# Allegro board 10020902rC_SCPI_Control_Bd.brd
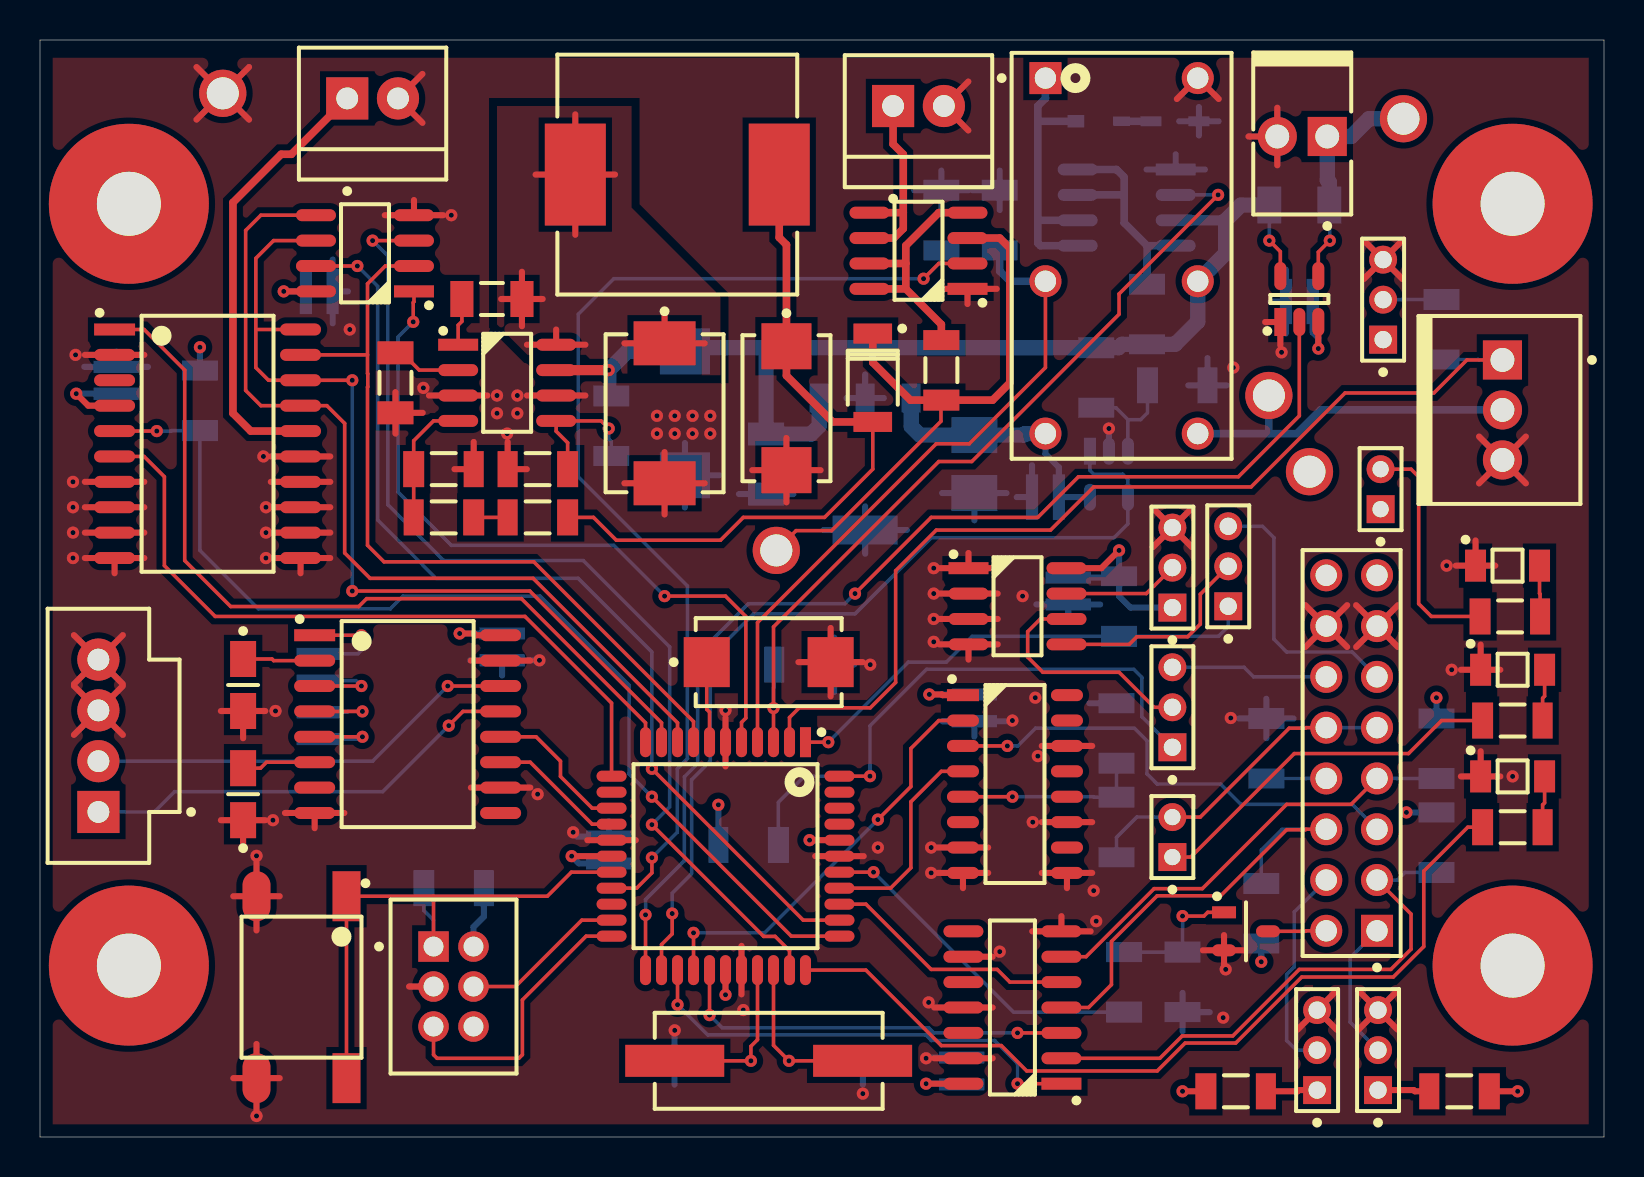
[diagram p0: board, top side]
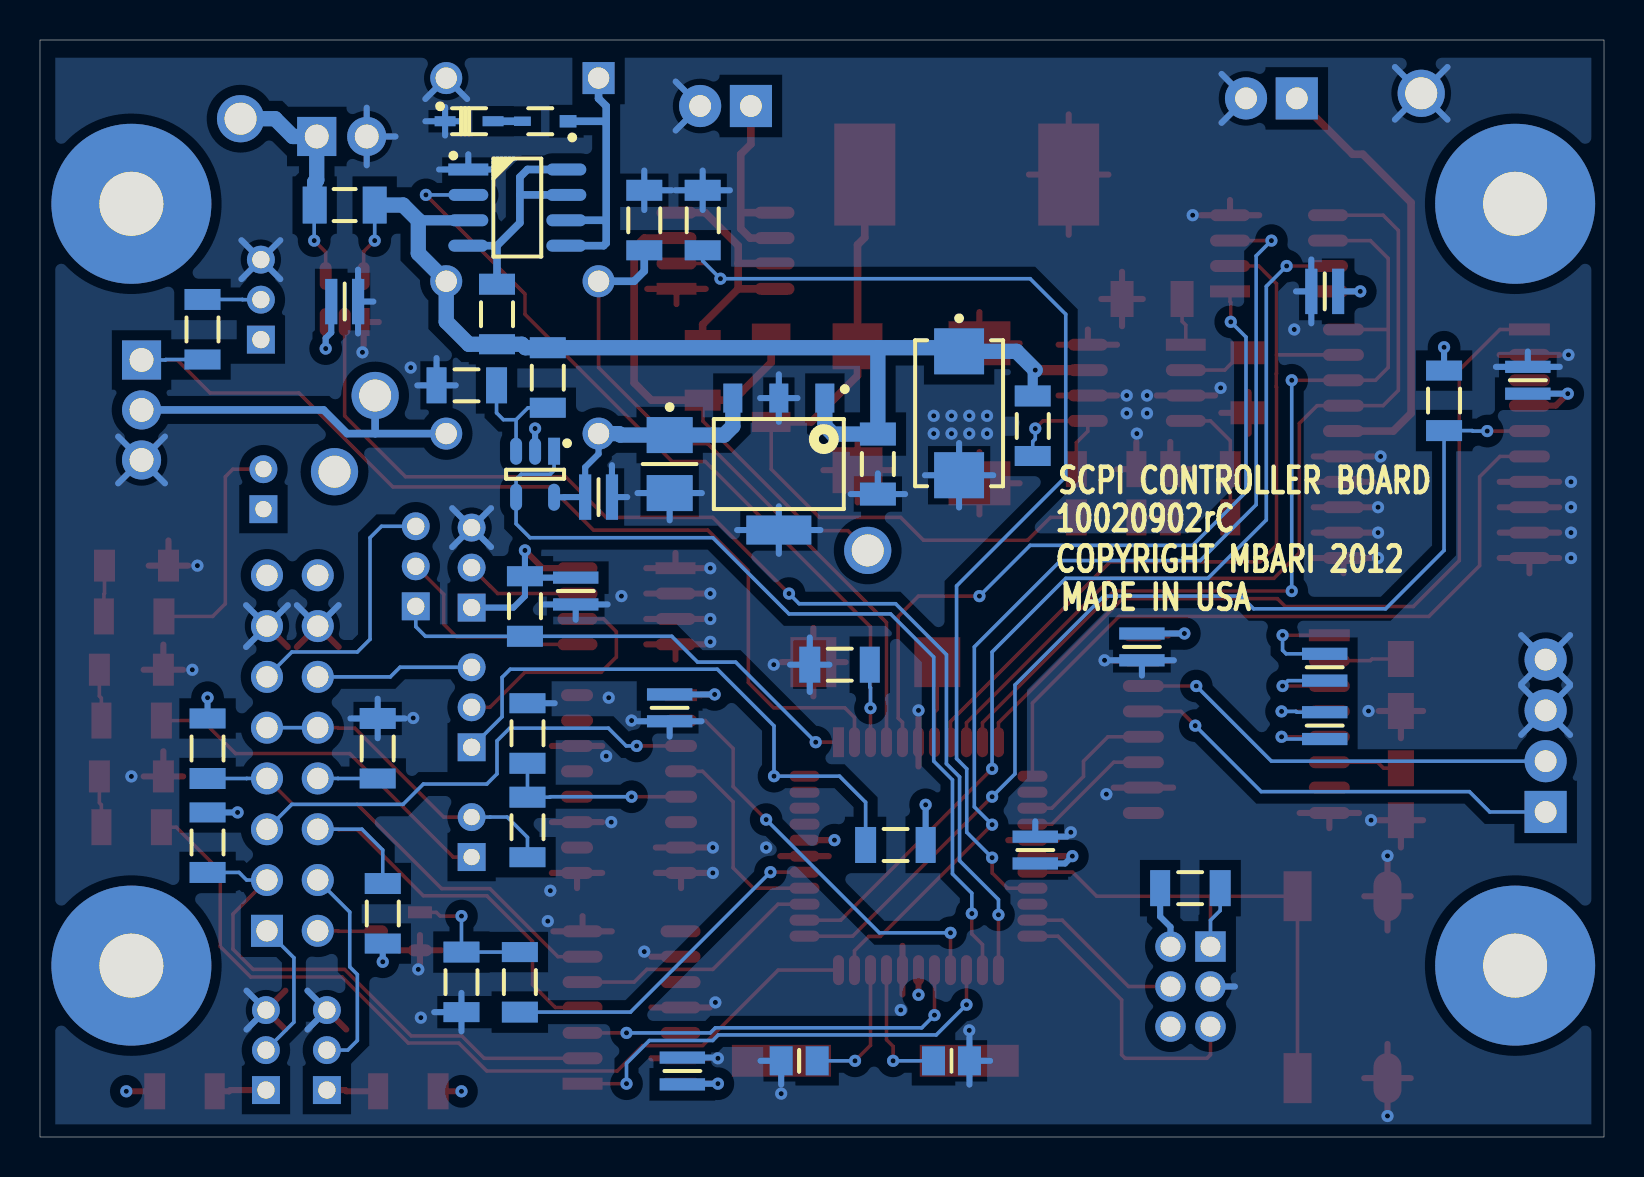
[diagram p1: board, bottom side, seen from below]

Outline 78.23 x 54.86 mm; copper layers: TOP, GND1, GND2, BOTTOM. Coordinates in mm from the lower left corner of the outline.
Outline path: 0,54.86 0,0 78.23,0 78.23,54.86 0,54.86

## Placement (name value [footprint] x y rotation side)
C1  0.1uF  [CAPC1320X76N]  28.45 14.35 90 bottom
C2  15pF  [CAPC2012X88N]  32.64 3.81 180 bottom
C3  15pF  [CAPC2012X88N]  40.26 3.81 0 bottom
C4  0.1uF  [CAPC1320X76N]  13.97 23.5 270 bottom
C5  0.1uF  [CAPC1320X76N]  13.97 20.57 270 bottom
C6  0.1uF  [CAPC1320X76N]  23.11 24.51 270 bottom
C7  0.1uF  [CAPMP3216X180N]  10.16 17.14 90 top
C8  0.1uF  [CAPMP3216X180N]  10.16 22.61 270 top
C9  10uF  [CAPMP7343X310N]  36.45 23.75 0 top
C10  0.1uF  [CAPC1320X76N]  13.97 42.29 180 bottom
C11  0.1uF  [CAPC1320X76N]  51.44 27.3 270 bottom
C12  0.1uF  [CAPC1320X76N]  46.1 3.3 90 bottom
C13  0.1uF  [CAPC1320X76N]  46.74 21.46 270 bottom
C14  0.1uF  [CAPC1320X76N]  3.81 37.85 90 bottom
C15  1.0uF  [CAPC3216X110N]  36.32 33.66 270 bottom
C16  10uF  [CAPMP3528X120N]  46.74 33.66 270 bottom
C17  0.1uF  [CAPC1320X76N]  62.99 41.78 180 bottom
C18  0.10uF  [CAPC3216X180N]  22.61 41.91 0 top
C19  100uF  [CAPMP7343X430N]  32.26 36.2 270 bottom
C20  68uF  [CAPMP7343X310N]  37.34 36.45 270 top
C21  0.10uF  [CAPC3216X180N]  17.78 37.72 270 top
C22  0.1uF  [CAPC1320X76N]  50.29 32 180 bottom
D1  LTST-C150KGKT  [LED_LTST-C150XXX]  73.66 23.37 0 top
D2  LTST-C150KGKT  [LED_LTST-C150XXX]  73.66 18.03 0 top
D3  LTST-C150KGKT  [LED_LTST-C150XXX]  73.41 28.57 0 top
D4  PMEG3050EP,115  [SODFL4725X110N]  41.66 37.97 270 top
D5  B550C-13-F  [DIOM7959X250N]  31.24 36.2 270 top
D6  BZX384-C3V3,115  [SOD2513X110N]  56.77 50.8 180 bottom
D7  DB2J31700L  [SODFL2513X80N]  52.96 50.8 0 bottom
J1  68602-116HLF  [HDRV16W64P254_2X8_858H]  66.88 10.31 90 top
J2  87831-0620  [MOLEX_87831-0620]  19.68 9.53 270 top
J3  70543-0003  [MOLEX_70543-4PIN]  2.92 20.07 270 top
J4  70543-0001  [MOLEX_70543-2PIN]  15.37 51.94 180 top
J5  1881558  [PHOENIX_1881558]  64.39 50.04 180 top
J6  70543-0001  [MOLEX_70543-2PIN]  42.67 51.56 180 top
J7  1881561  [PHOENIX_1881561]  73.15 38.86 270 top
JP1  951102-8622-AR  [HDRV2W50P200_1X2_H590]  56.64 14 90 top
JP2  951103-8622-AR  [HDRV3W50P200_1X3_H590]  63.88 2.35 90 top
JP3  951103-8622-AR  [HDRV3W50P200_1X3_H590]  66.93 2.35 90 top
JP4  951103-8622-AR  [HDRV3W50P200_1X3_H590]  59.44 26.54 90 top
JP5  951103-8622-AR  [HDRV3W50P200_1X3_H590]  56.64 19.49 90 top
JP6  951103-8622-AR  [HDRV3W50P200_1X3_H590]  56.64 26.48 90 top
JP7  951102-8622-AR  [HDRV2W50P200_1X2_H590]  67.06 31.4 90 top
JP8  951103-8622-AR  [HDRV3W50P200_1X3_H590]  67.18 39.88 90 top
K1  DSP2A-DC12V  [RELAY_DSP2A-NIL-XXXX]  54.1 44.07 0 top
L1  27uH  [IND_74770127]  31.88 48.13 0 top
NOREF  -  [unnamed]  4.45 46.67 0 top
NOREF#2  -  [#2]  0 0 0 top
NOREF#3  -  [#2]  0 0 90 top
NOREF#4  -  [unnamed]  73.66 46.67 0 top
NOREF#5  -  [#2]  -50.8 -76.2 0 top
NOREF#6  -  [#2]  4.45 46.67 0 top
NOREF#7  -  [#2]  1.91 148.59 0 top
NOREF#8  -  [#2]  0 0 0 top
NOREF#9  -  [#2]  0 0 90 top
NOREF#10  -  [unnamed]  73.66 8.57 0 top
NOREF#11  -  [#2]  73.66 8.57 90 top
NOREF#12  -  [unnamed]  4.45 8.57 0 top
Q1  BC847CLT1G  [SOT95P237X111-3N_132]  60.33 10.29 0 top
R1  10.0K  [RESC3216X60N]  69.85 14.73 90 bottom
R2  10.0K  [RESC3216X60N]  61.09 11.18 270 bottom
R3  10.0K  [RESC3216X60N]  69.85 19.43 90 bottom
R4  10.0K  [RESC3216X60N]  20.7 12.45 0 bottom
R5  1.00K  [RESC3216X60N]  61.34 19.43 270 bottom
R6  3.32K  [RESC3216X60N]  53.85 15.49 270 bottom
R7  6.81K  [RESC3216X60N]  53.85 20.19 90 bottom
R8  110  [RESC3216X60N]  73.66 20.83 0 top
R9  100.0K  [RESC3216X60N]  59.82 2.29 0 top
R10  1.00K  [RESC3216X60N]  54.23 7.75 90 bottom
R11  10.0K  [RESC3216X60N]  57.15 7.75 270 bottom
R12  100.0K  [RESC3216X60N]  70.99 2.29 180 top
R13  110  [RESC3216X60N]  73.66 15.49 0 top
R14  100.0K  [RESC3216X60N]  8 36.83 90 bottom
R15  10.0K  [RESC3216X60N]  53.98 26.54 90 bottom
R16  10.0K  [RESC3216X60N]  35.43 14.61 180 bottom
R17  59  [RESC3216X60N]  73.53 26.04 0 top
R18  0.02  [RESC3216X89N]  62.99 46.61 180 bottom
R19  121.0K  [RESC3216X60N]  52.83 37.97 270 bottom
R20  22.1K  [RESC3216X60N]  56.9 37.59 0 bottom
R21  10.0K  [RESC3216X60N]  45.09 38.35 90 top
R22  1.00M  [RESC3216X60N]  28.57 35.56 270 bottom
R23  TBD  [RESC3216X60N]  24.89 30.99 180 top
R24  10.0K  [RESC3216X60N]  45.09 45.85 270 bottom
R25  383.0K  [RESC3216X60N]  24.89 33.4 180 top
R26  36.5K  [RESC3216X60N]  20.19 30.99 180 top
R27  13.3K  [RESC3216X60N]  20.19 33.4 0 top
R28  100.0K  [RESC3216X60N]  70.1 40.39 270 bottom
R29  10.0K  [RESC3216X60N]  48.01 45.85 270 bottom
R30  10.0K  [RESC3216X60N]  55.37 41.15 270 bottom
R31  10.0K  [RESC3216X60N]  38.23 23.62 180 bottom
SW1  SWT6-V2M  [SW_SWT6-M]  13.08 7.49 270 top
TP1  YELLOW  [TP_KEYSTONE_5000S_COMP]  63.5 33.27 0 top
TP2  RED  [TP_KEYSTONE_5000S_COMP]  68.2 50.93 0 top
TP3  BLACK  [TP_KEYSTONE_5000S_COMP]  9.14 52.2 0 top
TP4  ORANGE  [TP_KEYSTONE_5000S_COMP]  36.83 29.34 0 top
TP5  GREEN  [TP_KEYSTONE_5000S_COMP]  61.47 37.08 0 top
U1  SN74LS07D  [SOIC127P600X175-14N]  48.64 6.48 180 top
U2  PIC24FJ64GA104-I/PT  [QFP80P1200X1200X120-44N]  34.29 14.05 270 top
U3  74HC4050D,653  [SOIC127P600X175-16N]  48.77 17.65 0 top
U4  MAX3232IDWR  [SOIC127P1030X265-16N]  18.39 20.65 0 top
U5  DS3234S#  [SOIC127P1032X265-20N]  8.38 34.67 0 top
U6  SST25VF080B-80-4I-SAE  [SOIC127P600X175-8N]  16.26 44.2 180 top
U7  24AA01-I/SN  [SOIC127P600X175-8N]  48.9 26.54 0 top
U8  MIC5209-3.3YS  [SOT230P700X180-4N]  41.27 33.66 270 bottom
U9  MAX4372FEUK+T  [SOT95P280X145-5N]  62.99 41.91 90 top
U10  AD8603AUJZ  [SOT95P280X100-5N]  53.47 33.15 270 bottom
U11  MAX5035DASA+  [SOIC127P600X175-8N]  23.37 37.72 0 top
U12  IRF7309TRPBF  [SOIC127P600X175-8N]  43.94 44.32 180 top
U13  IRF7309TRPBF  [SOIC127P600X175-8N]  54.36 46.48 180 bottom
Y1  3.6864MHz  [XTAL1140X480X430N]  36.45 3.81 0 top

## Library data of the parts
C1-C6 C10-C15 C17 C18 C21 C22 = CAP
C7-C9 C16 C19 C20 = CAP_P
D1-D3 = LED
D4 D5 = DIODE_SCHOTTKY
D6 = DIODE_ZENER
D7 = DIODE
J1 = CON16
J2 = CON6
J3 = CON4
J4-J6 = CON2
J7 = CON3
JP1 JP7 = JUMPER
JP2-JP6 JP8 = JUMPER3PIN_CENTER-TAP
K1 = RELAY_DSP2A-NIL-XXXX
L1 = IND_FERRITE
Q1 = BJT_NPN_BEC
R1-R31 = RES
SW1 = SW_SPST_13_24
TP1-TP5 = TESTPOINT
U1 = SN74LS07
U2 = PIC24FJxxGA104
U3 = 74HC4050
U4 = MAX3232
U5 = DS3234Sx
U6 = SST25VF080B
U7 = 24AA01SN
U8 = MIC5209-x.xxS
U9 = MAX4372xEUK-T_SYM-MOD1
U10 = AD8603
U11 = MAX5035
U12 U13 = IRF7309
Y1 = CRYSTAL

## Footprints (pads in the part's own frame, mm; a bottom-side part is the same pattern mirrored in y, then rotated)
CAPC1320X76N
  rect 0.61x2.271 smd: 1(-0.671,0) 2(0.671,0)
CAPC2012X88N
  rect 1.151x1.45 smd: 1(-0.899,0) 2(0.899,0)
CAPC3216X110N
  rect 1.151x1.801 smd: 1(-1.501,0) 2(1.501,0)
CAPC3216X180N
  rect 1.151x1.801 smd: 1(-1.501,0) 2(1.501,0)
CAPMP3216X180N
  rect 1.801x1.3 smd: 1(-1.3,0) 2(1.3,0)
CAPMP3528X120N
  rect 1.801x2.301 smd: 1(-1.45,0) 2(1.45,0)
CAPMP7343X310N
  rect 2.301x2.499 smd: 1(-3.099,0) 2(3.099,0)
CAPMP7343X430N
  rect 2.301x2.499 smd: 1(-3.099,0) 2(3.099,0)
DIOM7959X250N
  rect 2.2x3.099 smd: A(3.5,0) C(-3.5,0)
HDRV2W50P200_1X2_H590
  rect 1.397x1.397 hole 0.813: 1(0,0)
  round 1.397 hole 0.813: 2(1.999,0)
HDRV3W50P200_1X3_H590
  rect 1.397x1.397 hole 0.864: 1(0,0)
  round 1.397 hole 0.864: 2(1.999,0) 3(4,0)
HDRV16W64P254_2X8_858H
  rect 1.6x1.6 hole 1.067: 1(0,0)
  round 1.6 hole 1.067: 2(0,2.54) 3(2.54,0) 4(2.54,2.54) 5(5.08,0) 6(5.08,2.54) 7(7.62,0) 8(7.62,2.54) 9(10.16,0) 10(10.16,2.54) 11(12.7,0) 12(12.7,2.54) 13(15.24,0) 14(15.24,2.54) 15(17.78,0) 16(17.78,2.54)
IND_74770127
  rect 3.051x5.1 smd: 1(-5.1,0) 2(5.1,0)
LED_LTST-C150XXX
  rect 1.049x1.6 smd: A(1.6,0) C(-1.6,0)
MOLEX_70543-2PIN
  rect 2.108x2.108 hole 1.092: 1(0,0)
  round 2.108 hole 1.092: 2(-2.54,0)
MOLEX_70543-4PIN
  rect 2.108x2.108 hole 1.092: 1(3.81,0)
  round 2.108 hole 1.092: 2(1.27,0) 3(-1.27,0) 4(-3.81,0)
MOLEX_87831-0620
  rect 1.524x1.524 hole 0.991: 1(0,0)
  round 1.524 hole 0.991: 2(0,1.999) 3(1.999,0) 4(1.999,1.999) 5(4,0) 6(4,1.999)
PHOENIX_1881558
  rect 1.956x1.956 hole 1.194: 1(0,0)
  round 1.956 hole 1.194: 2(2.499,0)
PHOENIX_1881561
  rect 1.956x1.956 hole 1.194: 1(0,0)
  round 1.956 hole 1.194: 2(2.499,0) 3(5.001,0)
QFP80P1200X1200X120-44N
  rect 1.501x0.551 smd: 1(-5.7,4)
  oval 1.501x0.551 smd: 2(-5.7,3.2) 3(-5.7,2.4) 4(-5.7,1.6) 5(-5.7,0.8) 6(-5.7,0) 7(-5.7,-0.8) 8(-5.7,-1.6) 9(-5.7,-2.4) 10(-5.7,-3.2) 11(-5.7,-4) 23(5.7,-4) 24(5.7,-3.2) 25(5.7,-2.4) 26(5.7,-1.6) 27(5.7,-0.8) 28(5.7,0) 29(5.7,0.8) 30(5.7,1.6) 31(5.7,2.4) 32(5.7,3.2) 33(5.7,4)
  oval 0.551x1.501 smd: 12(-4,-5.7) 13(-3.2,-5.7) 14(-2.4,-5.7) 15(-1.6,-5.7) 16(-0.8,-5.7) 17(0,-5.7) 18(0.8,-5.7) 19(1.6,-5.7) 20(2.4,-5.7) 21(3.2,-5.7) 22(4,-5.7) 34(4,5.7) 35(3.2,5.7) 36(2.4,5.7) 37(1.6,5.7) 38(0.8,5.7) 39(0,5.7) 40(-0.8,5.7) 41(-1.6,5.7) 42(-2.4,5.7) 43(-3.2,5.7) 44(-4,5.7)
RELAY_DSP2A-NIL-XXXX
  rect 1.6x1.6 hole 1.067: 1(-3.81,8.89)
  round 1.6 hole 1.067: 5(-3.81,-1.27) 8(-3.81,-8.89) 9(3.81,-8.89) 12(3.81,-1.27) 16(3.81,8.89)
RESC3216X60N
  rect 1.049x1.801 smd: 1(-1.501,0)
  rect 1.001x1.801 smd: 2(1.501,0)
RESC3216X89N
  rect 1.199x1.849 smd: 1(-1.501,0) 2(1.501,0)
SOD2513X110N
  rect 1.049x0.5 smd: A(1.199,0) C(-1.199,0)
SODFL2513X80N
  rect 0.841x0.47 smd: A(1.14,0)
  rect 0.841x0.62 smd: C(-1.14,0)
SODFL4725X110N
  rect 1.001x1.93 smd: A(2.21,0) C(-2.21,0)
SOIC127P600X175-8N
  rect 1.999x0.599 smd: 1(-2.451,1.905)
  oval 1.999x0.599 smd: 2(-2.451,0.635) 3(-2.451,-0.635) 4(-2.451,-1.905) 5(2.451,-1.905) 6(2.451,-0.635) 7(2.451,0.635) 8(2.451,1.905)
SOIC127P600X175-14N
  rect 1.999x0.599 smd: 1(-2.451,3.81)
  oval 1.999x0.599 smd: 2(-2.451,2.54) 3(-2.451,1.27) 4(-2.451,0) 5(-2.451,-1.27) 6(-2.451,-2.54) 7(-2.451,-3.81) 8(2.451,-3.81) 9(2.451,-2.54) 10(2.451,-1.27) 11(2.451,0) 12(2.451,1.27) 13(2.451,2.54) 14(2.451,3.81)
SOIC127P600X175-16N
  rect 1.6x0.599 smd: 1(-2.601,4.445)
  oval 1.6x0.599 smd: 2(-2.601,3.175) 3(-2.601,1.905) 4(-2.601,0.635) 5(-2.601,-0.635) 6(-2.601,-1.905) 7(-2.601,-3.175) 8(-2.601,-4.445) 9(2.601,-4.445) 10(2.601,-3.175) 11(2.601,-1.905) 12(2.601,-0.635) 13(2.601,0.635) 14(2.601,1.905) 15(2.601,3.175) 16(2.601,4.445)
SOIC127P1030X265-16N
  rect 2.05x0.599 smd: 1(-4.651,4.445)
  oval 2.05x0.599 smd: 2(-4.651,3.175) 3(-4.651,1.905) 4(-4.651,0.635) 5(-4.651,-0.635) 6(-4.651,-1.905) 7(-4.651,-3.175) 8(-4.651,-4.445) 9(4.651,-4.445) 10(4.651,-3.175) 11(4.651,-1.905) 12(4.651,-0.635) 13(4.651,0.635) 14(4.651,1.905) 15(4.651,3.175) 16(4.651,4.445)
SOIC127P1032X265-20N
  rect 2.05x0.599 smd: 1(-4.651,5.715)
  oval 2.05x0.599 smd: 2(-4.651,4.445) 3(-4.651,3.175) 4(-4.651,1.905) 5(-4.651,0.635) 6(-4.651,-0.635) 7(-4.651,-1.905) 8(-4.651,-3.175) 9(-4.651,-4.445) 10(-4.651,-5.715) 11(4.651,-5.715) 12(4.651,-4.445) 13(4.651,-3.175) 14(4.651,-1.905) 15(4.651,-0.635) 16(4.651,0.635) 17(4.651,1.905) 18(4.651,3.175) 19(4.651,4.445) 20(4.651,5.715)
SOT95P237X111-3N_132
  rect 1.199x0.599 smd: 1(-1.1,0.95)
  oval 1.199x0.599 smd: 2(-1.1,-0.95) 3(1.1,0)
SOT95P280X100-5N
  rect 1.349x0.599 smd: 1(-1.151,0.95)
  oval 1.349x0.599 smd: 2(-1.151,0) 3(-1.151,-0.95) 4(1.151,-0.95) 5(1.151,0.95)
SOT95P280X145-5N
  rect 1.4x0.599 smd: 1(-1.151,0.95)
  oval 1.4x0.599 smd: 2(-1.151,0) 3(-1.151,-0.95) 4(1.151,-0.95) 5(1.151,0.95)
SOT230P700X180-4N
  rect 1.45x0.95 smd: 1(-3.299,2.301) 2(-3.299,0) 3(-3.299,-2.301)
  rect 1.45x3.251 smd: 4(3.299,0)
SW_SWT6-M
  rect 2.499x1.4 smd: 1(-4.549,2.25) 3(4.549,2.25)
  oval 2.499x1.4 smd: 2(-4.549,-2.25) 4(4.549,-2.25)
TP_KEYSTONE_5000S_COMP
  round 2.362 hole 1.6: 1(0,0)
unnamed
  round 8.001 hole 3.2: (0,0)
XTAL1140X480X430N
  rect 4.95x1.6 smd: 1(-4.699,0) 2(4.699,0)

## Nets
3.3V: C1.1 C6.1 C10.2 C11.1 C12.1 C13.1 C14.1 C16.1 C17.1 C22.1 J2.2 JP6.1 JP7.1 JP8.1 K1.8(B1) R1.2 R2.2 R3.2 R4.2 R9.1 R12.1 R14.2 R15.2 R16.2 TP1.1(TP) U1.14(VCC) U2.17(AVDD) U2.28(VDD_1) U2.40(VDD_2) U3.1(VCC) U4.16(VCC) U5.4(VCC) U6.8(VDD) U7.8(VCC) U8.3(OUT) U9.3(VCC) U10.5(V+)
GND_SIGNAL: C1.2 C2.2 C3.2 C6.2 C7.1 C8.2 C9.2 C10.1 C11.2 C12.2 C13.2 C14.2 C15.2 C16.2 C17.2 C19.2 C20.2 C21.2 C22.2 D1.C D2.C D3.C D5.A D6.C J1.13 J1.14 J2.3 J3.3 J3.4 J4.2 J5.2 J6.2 J7.3 JP2.3 JP3.3 JP6.3 JP8.3 K1.16(COIL-) Q1.2(E) R5.1 R7.2 R11.2 R20.2 R24.1 R25.2 R27.2 R29.1 R31.1 SW1.2 SW1.4 TP3.1(TP) U1.7(GND) U1.9(4A) U1.11(5A) U1.13(6A) U2.6(DISVREG) U2.16(AVSS) U2.29(VSS_1) U2.39(VSS_2) U3.7(3A) U3.8(GND) U3.9(4A) U3.11(5A) U3.14(6A) U4.8(R2IN) U4.10(DIN2) U4.15(GND) U5.2(NC2) U5.7(NC7) U5.8(NC8) U5.9(NC9) U5.10(NC10) U5.11(NC11) U5.12(NC12) U5.13(NC13) U5.14(NC14) U5.15(GND) U6.4(VSS) U7.1(A0) U7.2(A1) U7.3(A2) U7.4(GND) U8.2(GND) U8.4(\) U9.1(GND) U10.2(V-) U11.3(SGND) U11.6(GND) U12.1(S1) U13.1(S1)
BATT: C15.1 C19.1 K1.12(A2) R18.2 R19.1 R22.1 R30.2 U8.1(IN) U9.5(RS-) U11.7(VIN) U13.3(S2)
BATT_CURR: U2.23(AN4/C1INB/RP2/SDA2/CN6/RB2) U9.2(OUT)
BATT_VOLT: U2.24(AN5/C1INA/RP3/SCL2/CN7/RB3) U10.1(OUT) U10.4(IN-)
CAM_ON_OFF: R24.2 U2.19(AN0/C3INC/VREF+/CN2/CTED1/RA0) U12.2(G1)
LED_CNTL: R31.2 U2.3(RP23/CN17/PMA0/RC7) U13.2(G1)
LED_STATE: K1.5(A1) R29.2 U2.4(RP24/CN20/PMA5/RC8)
LED_TRIG: J7.1 R28.2 U2.2(RP22/CN18/PMA1/RC6)
N14907254: J2.1 R4.1 SW1.1 SW1.3 U2.18(MCLR*)
N14907334: U1.1(1A) U2.25(AN6/RP16/CN8/RC0)
N14907346: U2.26(AN7/RP17/CN9/RC1) U3.2(1Y)
N14907358: U1.3(2A) U2.27(AN8/RP18/PMA2/CN10/RC2)
N14907370: U1.5(3A) U2.36(RP19/CN28/PMBE/RC3)
N14907460: Q1.1(B) R10.2 R11.1
N14907464: R10.1 U2.38(RP21/CN26/PMA3/RC5)
N14907857: J1.2 Q1.3(C)
N14907883: J1.3 R1.1 U1.2(1Y)
N14907926: J1.5 U3.3(1A)
N14907967: J1.6 R2.1 U1.4(2Y)
N14907987: J1.7 R3.1 U1.6(3Y)
N14908751: JP2.1 R9.2
N14908758: JP3.1 R12.2
N14908817: J1.1 JP3.2
N14908823: J1.4 JP2.2
N14908912: JP4.2 U7.5(SDA)
N14908949: JP5.2 U7.6(SCL)
N14908956: JP4.1 R15.1 U2.1(RP9/SDA1/CN21/PMD3/RB9)
N14909000: JP5.1 R16.1 U2.44(RP8/SCL1/CN22/PMD4/RB8)
N14909094: J1.11 JP4.3
N14909112: J1.12 JP5.3
N14910852: C3.1 U2.31(OSCO/CLKO/CN29/RA3) Y1.2
N14910856: C2.1 U2.30(OSCI/CLKI/C1IND/CN30/RA2) Y1.1
N14911169: C4.1 U4.1(C+)
N14911173: C5.1 U4.4(C2+)
N14911187: C4.2 U4.3(C1-)
N14911204: C5.2 U4.5(C2-)
N14911399: C7.2 U4.6(V-)
N14911406: C8.1 U4.2(V+)
N14911585: R6.1 R7.1 U3.5(2A)
N14911707: J1.9 J1.10 JP1.2 R6.2
N14911875: J1.8 R5.2
N14916159: JP6.2 U7.7(WP)
N14918456: J3.2 U4.14(DOUT1)
N14918460: J3.1 U4.13(R1IN)
N14934806: U2.14(AN10/C3INB/CVREF/RTCC/RP14/CN12) U4.12(R1OUT)
N14934816: U2.15(AN9/C3INA/RP15/CN11/RB15) U4.11(DIN1)
N14937836: J4.1 U5.16(VBAT)
N14938943: D1.A R8.2
N14940001: C9.1 U2.7(VCAP/VDDCORE)
N14968686: D2.A R13.2
N14976351: U2.10(AN12/RP12/CN14/PMD0/RB12) U5.18(SCLK_1) U5.20(SCLK_0) U6.6(SCK)
N14991516: D4.C R21.1 TP4.1(TP) U12.3(S2)
N14991548: J6.1 U12.5(D2B) U12.6(D2A)
N14991564: R21.2 U12.4(G2) U12.7(D1B) U12.8(D1A)
N14993015: D3.A R17.2
N14993095: J5.1 R18.1 TP2.1(TP) U9.4(RS+)
N14993373: R19.2 R20.1 U10.3(IN+)
N14997505: D7.C(CATHODE) K1.1(COIL+) U13.5(D2B) U13.6(D2A)
N14997509: R30.1 U13.4(G2) U13.7(D1B) U13.8(D1A)
N14997545: J7.2 K1.9(B2) TP5.1(TP)
N14997611: JP8.2 R28.1
N14997833: D6.A D7.A(ANODE)
N15001299: J2.5 U2.22(PGEC1/AN3/C2INA/RP1/CN5/RB1)
N15001311: J2.4 U2.21(PGED1/AN2/C2INB/RP0/CN4/RB0)
N15003009: U2.37(RP20/CN25/PMA4/RC4) U3.4(2Y)
N15003605: U2.11(AN11/C1INC/RP13/PMRD/REFO/CN13/) U5.1(C\S\)
N15003639: U2.9(PGEC2/RP11/CN15/PMD1/RB11) U5.17(DIN) U6.5(SI)
N15003651: U2.8(PGED2/RP10/CN16/PMD2/RB10) U5.19(DOUT) U6.2(SO)
N15003663: U2.12(TMS/PMA10/RA10) U5.6(R\S\T\)
N15007328: JP7.2 R17.1
N15010506: C18.2 D5.C L1.1 U11.8(LX)
N15010522: C20.1 D4.A L1.2 R23.1
N15010535: R26.2 R27.1 U11.4(FB)
N15010979: C21.1 U11.2(VD)
N15011317: C18.1 U11.1(BST)
N15011830: R22.2 R25.1 U11.5(ON/\O\F\F\)
N15012683: R13.1 U2.33(SOSCI/C1IND/RP4/CN1/RB4)
N15013353: JP1.1 R8.1
N15018313: U2.5(RP25/CN19/PMA6/RC9) U6.1(CE#)
N15018357: U2.35(TDI/PMA9/RA9) U6.7(HOLD#)
N15018369: U2.32(TDO/PMA8/RA8) U6.3(WP#)
N15023556: R14.1 U2.34(SOSCO/SCLK1/T1CK/C2INC/CN0/RA4) U5.5(I\N\T\/SQW)
N15039082: R23.2 R26.1

Pads without a net: J1 15 16; J2 6; U1 8 10 12; U2 13 20 41 42 43; U3 6 10 12 13 15 16; U4 7 9; U5 3

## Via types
v1: diameter 0.61, hole 0.254, TOP to BOTTOM, 121 vias

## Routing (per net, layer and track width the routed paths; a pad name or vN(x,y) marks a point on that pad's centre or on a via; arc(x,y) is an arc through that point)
3.3V: length 325.1
  TOP w0.305: U2.28 v1(34.29,7.11) ; v1(44.49,22.13) 45.11,22.13 45.15,22.1 U3.1 ; R9.1 v1(57.15,2.29) ; R12.1 v1(73.91,2.29) ; v1(1.81,37.18) 2.41,36.58 U5.4 ; U2.40 v1(38.49,14.85) ; U4.16 21.8,25.1 21.71,25.18 v1(20.99,25.18) ; U1.14 v1(44.32,2.67) ; U2.17 v1(26.59,14.05) ; U7.8 53.09,28.45 v1(53.98,29.34) ; U9.3 v1(63.94,39.43) ; U6.8 v1(12.19,42.29)
  GND2 w0.762: 66.8,36.58 66.8,36.58 v1(63.94,39.43) ; 66.8,36.58 67.18,36.96 JP8.1 ; 66.8,36.58 TP1.1 ; 69.98,16.23 69.98,12.06 68.83,10.92 68.83,6.14 71.04,2.86 73.34,2.86 v1(73.91,2.29) ; 69.98,16.23 70.72,16.23 71.88,17.4 71.88,21.97 ; 69.98,16.23 v1(68.35,16.23) ; TP1.1 53.59,33.27 51.69,35.18 K1.8 50.29,29.34 ; TP1.1 65.37,31.4 JP7.1 69.69,31.4 71.88,29.21 71.88,21.97 ; 32.89,23.88 32.89,19.96 33.93,18.92 ; 32.89,23.88 39.12,23.88 40.22,24.97 42.08,24.97 43.69,23.37 44.45,23.37 ; 32.89,23.88 28.19,23.88 ; 24.51,14.05 24.51,10.41 23.62,9.53 J2.2 ; 24.51,14.05 v1(26.59,14.05) ; 24.51,14.05 23.37,15.19 23.37,19.05 28.19,23.88 ; 57.15,7.18 57.21,7.24 60.38,7.24 61.09,7.95 v1(61.09,8.76) ; 57.15,7.18 56.71,6.73 46.61,6.73 ; 57.15,7.18 v1(57.15,2.29) ; 33.93,18.92 35.44,18.92 36.68,17.68 36.68,14.85 ; 33.93,18.92 v1(33.93,16.61) ; 50.29,29.34 v1(53.98,29.34) ; 50.29,29.34 50.29,26.54 ; 22.67,29.4 20.99,27.71 v1(20.99,25.18) ; 22.67,29.4 19.43,32.64 12.45,32.64 ; 22.67,29.4 28.19,23.88 ; 71.88,21.97 v1(69.85,21.97) ; v1(44.49,22.13) 44.45,22.17 44.45,23.37 ; 46.61,23.37 46.61,6.73 ; 46.61,23.37 44.45,23.37 ; 46.61,23.37 47.12,23.37 50.29,26.54 ; 46.61,6.73 46.61,4.14 45.14,2.67 v1(44.32,2.67) ; v1(1.81,37.18) 1.81,34.64 3.81,32.64 8,32.64 ; 36.68,14.85 v1(38.49,14.85) ; 36.68,14.85 36.68,9.5 v1(34.29,7.11) ; 12.45,32.64 12.45,41.22 12.19,41.48 v1(12.19,42.29) ; 12.45,32.64 8,32.64 ; 8,32.64 v1(8,39.5) ; 50.29,26.54 50.36,26.48 JP6.1
  BOTTOM w0.305: R14.2 v1(8,39.5) ; R15.2 53.98,27.05 54.55,26.48 JP6.1 ; R15.2 v1(53.98,29.34) ; R15.2 53.91,27.98 C11.1 ; v1(12.19,42.29) C10.2 ; C17.1 63.66,40.23 63.94,39.95 v1(63.94,39.43) ; v1(26.59,14.05) 26.96,13.68 C1.1 ; U10.5 52,32 51.99,32 C22.1 50.96,33.49 50.29,34.16 K1.8 ; C13.1 v1(44.49,22.13) ; R4.2 22.2,11.02 21.68,10.51 J2.2 ; R3.2 v1(69.85,21.97) ; R1.2 v1(68.35,16.23) ; R2.2 v1(61.09,8.76) ; C6.1 v1(20.99,25.18) ; C12.1 46.07,2.67 v1(44.32,2.67) ; C14.1 v1(1.81,37.18) ; R16.2 v1(33.93,16.61)
  BOTTOM w0.762: U8.3 43.58,35.54 44.02,35.11 C16.1 49.2,35.11 49.28,35.18 K1.8
GND_SIGNAL: length 570.1
  TOP w0.305: J7.3 74.32,32.69 ; J7.3 71.98,32.69 ; J7.3 71.98,35.03 ; J7.3 74.32,35.03 ; 66.21,42.91 JP8.3 ; JP8.3 66.21,44.85 ; JP8.3 68.15,42.91 ; JP8.3 68.15,44.85 ; SW1.2 10.83,13.75 ; SW1.2 9.67,12.04 ; SW1.2 11.99,12.04 ; SW1.2 10.83,10.33 ; 11.55,34.04 U5.15 14.52,34.04 ; J1.13 67.92,24.51 ; J1.13 67.92,26.6 ; J1.13 65.83,24.51 ; J1.13 65.83,26.6 ; 2.25,32.77 U5.7 5.22,32.77 ; 44.98,28.45 U7.1 ; U7.1 46.44,29.21 ; U7.1 47.9,28.45 ; U12.1 47.85,42.42 ; U12.1 44.93,42.42 ; U12.1 46.39,41.66 ; U5.10 5.22,28.96 ; U5.10 2.25,28.96 ; U5.10 3.73,28.2 ; 46.17,12.45 U3.8 ; U3.8 44.91,13.21 ; U3.8 47.43,13.21 ; JP6.3 57.61,31.45 ; JP6.3 55.67,31.45 ; JP6.3 57.61,29.51 ; JP6.3 55.67,29.51 ; C8.2 11.27,21.31 ; C8.2 9.05,21.31 ; C8.2 10.16,19.94 ; 19.46,37.08 U11.3 22.38,37.08 ; 14.52,31.5 U5.13 11.55,31.5 ; 51.37,12.45 U3.9 ; U3.9 50.11,13.21 ; U3.9 52.63,13.21 ; D3.C 72.79,28.57 ; D3.C 70.82,28.57 ; D3.C 71.81,29.83 ; 24.36,37.08 U11.6 27.28,37.08 ; C20.2 39.05,33.35 ; C20.2 37.34,34.96 ; C20.2 37.34,31.74 ; C20.2 35.63,33.35 ; SW1.4 10.83,4.65 ; SW1.4 11.99,2.94 ; SW1.4 9.67,2.94 ; SW1.4 10.83,1.23 ; C21.2 19.14,36.22 ; C21.2 17.78,35.18 ; C21.2 17.78,37.25 ; 47.9,27.18 U7.2 44.98,27.18 ; JP3.3 67.9,5.38 ; JP3.3 65.96,7.32 ; JP3.3 65.96,5.38 ; JP3.3 67.9,7.32 ; 35.09,7.13 U2.29 35.09,9.56 ; 20.73,33.4 R27.2 21.69,34.76 ; 49.63,10.29 U1.7 ; U1.7 52.55,10.29 ; U1.7 51.09,11.05 ; 44.73,3.94 47.65,3.94 ; 19.13,50.72 J4.2 19.13,53.16 ; 59.23,8.58 Q1.2 ; Q1.2 60.28,9.34 ; Q1.2 59.23,10.1 ; Q1.2 58.17,9.34 ; J3.3 4.14,20.11 ; J3.3 1.7,22.56 ; J3.3 1.7,20.11 ; J3.3 4.14,22.56 ; 2.25,39.12 U5.2 5.22,39.12 ; U4.8 15.22,16.21 ; U4.8 13.74,15.45 ; U4.8 12.25,16.21 ; 23.39,34.76 R25.2 24.35,33.4 ; 11.55,28.96 U5.11 ; U5.11 13.03,28.2 ; U5.11 14.52,28.96 ; 29.8,14.85 U2.16 27.38,14.85 ; 24.53,17.48 U4.10 21.55,17.48 ; 5.22,31.5 U5.8 2.25,31.5 ; U6.4 18.71,46.86 ; U6.4 20.17,46.1 ; U6.4 17.25,46.1 ; 7.83,50.88 TP3.1 ; TP3.1 10.46,53.51 ; TP3.1 10.46,50.88 ; TP3.1 7.83,53.51 ; 34.29,20.96 U2.6 34.29,18.53 ; 58.96,51.92 K1.16 56.87,51.92 ; 10.16,14.48 C7.1 ; C7.1 11.27,15.84 ; C7.1 9.05,15.84 ; J3.4 4.14,25.1 ; J3.4 4.14,22.65 ; J3.4 1.7,22.65 ; J3.4 1.7,25.1 ; 62.04,39.6 U9.1 61.28,40.76 ; 61.89,48.6 J5.2 ; J5.2 60.45,50.04 ; J5.2 61.89,51.48 ; 63.29,24.51 J1.14 ; J1.14 65.38,26.6 ; J1.14 63.29,26.6 ; J1.14 65.38,24.51 ; 38.78,14.05 U2.39 41.2,14.05 ; D5.A 33.25,32.69 ; D5.A 31.24,34.25 ; D5.A 31.24,31.14 ; D5.A 29.23,32.69 ; 11.55,32.77 U5.14 14.52,32.77 ; JP2.3 64.85,5.38 ; JP2.3 62.91,5.38 ; JP2.3 64.85,7.32 ; D2.C 73.05,18.03 ; D2.C 71.07,18.03 ; D2.C 72.06,19.29 ; U1.9 47.65,9.02 ; 52.63,19.56 U3.14 50.11,19.56 ; 47.9,25.91 U7.3 44.98,25.91 ; 46.43,50.34 J6.2 46.43,52.78 ; C9.2 41.16,23.75 ; C9.2 39.55,22.04 ; C9.2 37.94,23.75 ; C9.2 39.55,25.46 ; D1.C 72.06,24.63 ; D1.C 71.07,23.37 ; D1.C 73.05,23.37 ; 47.65,6.48 U1.11 44.73,6.48 ; 44.98,24.64 U7.4 ; U7.4 46.44,23.88 ; U7.4 47.9,24.64 ; 11.55,30.23 U5.12 14.52,30.23 ; 21.55,23.83 U4.15 24.53,23.83 ; 2.25,30.23 U5.9 5.22,30.23 ; 50.11,15.75 U3.11 52.63,15.75 ; 47.43,14.48 U3.7 44.91,14.48 ; 18.46,7.53 J2.3
  GND1 w0.305: 66.21,42.91 JP8.3 ; JP8.3 68.15,42.91 ; JP8.3 66.21,44.85 ; JP8.3 68.15,44.85 ; J4.2 19.13,53.16 ; J4.2 16.69,53.16 ; J4.2 19.13,50.72 ; J4.2 16.69,50.72 ; J3.3 4.14,20.11 ; J3.3 4.14,22.56 ; J3.3 1.7,20.11 ; J3.3 1.7,22.56 ; 65.96,5.38 JP3.3 ; JP3.3 65.96,7.32 ; JP3.3 67.9,5.38 ; JP3.3 67.9,7.32 ; J7.3 74.32,32.69 ; J7.3 71.98,32.69 ; J7.3 74.32,35.03 ; J7.3 71.98,35.03 ; 62.91,5.38 JP2.3 ; JP2.3 64.85,5.38 ; JP2.3 64.85,7.32 ; JP2.3 62.91,7.32 ; J3.4 4.14,25.1 ; J3.4 1.7,25.1 ; J3.4 1.7,22.65 ; J3.4 4.14,22.65 ; 65.83,26.6 J1.13 ; J1.13 67.92,26.6 ; J1.13 67.92,24.51 ; J1.13 65.83,24.51 ; J6.2 46.43,50.34 ; J6.2 46.43,52.78 ; J6.2 43.99,50.34 ; J6.2 43.99,52.78 ; 18.46,7.53 J2.3 ; 56.87,51.92 K1.16 58.96,51.92 ; 60.45,50.04 J5.2 ; J5.2 61.89,51.48 ; J5.2 61.89,48.6 ; TP3.1 10.46,50.88 ; TP3.1 10.46,53.51 ; TP3.1 7.83,50.88 ; TP3.1 7.83,53.51 ; 63.29,24.51 J1.14 ; J1.14 65.38,26.6 ; J1.14 65.38,24.51 ; J1.14 63.29,26.6 ; 55.67,29.51 JP6.3 ; JP6.3 55.67,31.45 ; JP6.3 57.61,31.45 ; JP6.3 57.61,29.51
  GND2 w0.305: 71.98,35.03 J7.3 ; J7.3 74.32,32.69 ; J7.3 71.98,32.69 ; J7.3 74.32,35.03 ; 7.83,53.51 TP3.1 ; TP3.1 10.46,53.51 ; TP3.1 10.46,50.88 ; TP3.1 7.83,50.88 ; J4.2 19.13,50.72 ; J4.2 16.69,53.16 ; J4.2 16.69,50.72 ; J4.2 19.13,53.16 ; 43.99,50.34 J6.2 ; J6.2 46.43,52.78 ; J6.2 46.43,50.34 ; J6.2 43.99,52.78 ; JP6.3 57.61,31.45 ; JP6.3 57.61,29.51 ; JP6.3 55.67,29.51 ; JP6.3 55.67,31.45 ; 60.45,50.04 J5.2 ; J5.2 61.89,48.6 ; J5.2 61.89,51.48 ; 62.91,7.32 JP2.3 ; JP2.3 64.85,5.38 ; JP2.3 62.91,5.38 ; JP2.3 64.85,7.32 ; J1.14 65.38,24.51 ; J1.14 63.29,24.51 ; J1.14 65.38,26.6 ; J1.14 63.29,26.6 ; JP3.3 67.9,7.32 ; JP3.3 65.96,7.32 ; JP3.3 67.9,5.38 ; JP3.3 65.96,5.38 ; 1.7,22.56 J3.3 ; J3.3 4.14,22.56 ; J3.3 4.14,20.11 ; J3.3 1.7,20.11 ; 65.83,24.51 J1.13 ; J1.13 67.92,24.51 ; J1.13 65.83,26.6 ; J1.13 67.92,26.6 ; J3.4 4.14,22.65 ; J3.4 1.7,25.1 ; J3.4 4.14,25.1 ; J3.4 1.7,22.65 ; 66.21,44.85 JP8.3 ; JP8.3 66.21,42.91 ; JP8.3 68.15,42.91 ; JP8.3 68.15,44.85 ; 56.87,51.92 K1.16 58.96,51.92 ; 18.46,7.53 J2.3
  BOTTOM w0.305: J3.4 4.14,25.1 ; J3.4 1.7,22.65 ; J3.4 1.7,25.1 ; J3.4 4.14,22.65 ; 65.38,26.6 J1.14 63.29,26.6 ; U10.2 v1(53.47,35.43) ; 62.32,40.19 C17.2 ; C17.2 62.32,43.38 ; C17.2 61.56,41.78 ; 23.11,23.08 C6.2 ; C6.2 24.71,23.84 ; C6.2 21.52,23.84 ; 1.7,20.11 J3.3 ; J3.3 4.14,22.56 ; J3.3 1.7,22.56 ; J3.3 4.14,20.11 ; C16.2 48.35,32.2 ; C16.2 46.74,30.84 ; C16.2 45.13,32.2 ; 7.83,50.88 TP3.1 ; TP3.1 10.46,53.51 ; TP3.1 7.83,53.51 ; TP3.1 10.46,50.88 ; R24.1 46.45,47.35 ; R24.1 45.09,48.33 ; R24.1 45.09,46.36 ; R24.1 43.72,47.35 ; C15.2 37.68,32.15 ; C15.2 36.32,33.19 ; C15.2 34.96,32.15 ; D6.C 57.97,51.51 ; D6.C 57.97,50.09 ; D6.C 56.98,50.8 ; D6.C 58.95,50.8 ; C13.2 48.33,20.79 ; C13.2 46.74,20.03 ; C13.2 45.14,20.79 ; 61.34,19.95 R5.1 ; R5.1 61.34,21.92 ; R5.1 59.98,20.93 ; R5.1 62.7,20.93 ; 28.45,15.79 C1.2 26.85,15.02 ; 40.34,36.95 U8.2 ; U8.2 42.21,36.95 ; U8.2 41.27,35.77 ; U8.2 41.27,38.14 ; C14.2 3.81,39.28 ; C14.2 2.21,38.52 ; C14.2 5.41,38.52 ; 55.67,29.51 JP6.3 ; JP6.3 57.61,31.45 ; JP6.3 57.61,29.51 ; JP6.3 55.67,31.45 ; 30.7,3.81 C2.2 ; C2.2 31.74,2.62 ; C2.2 31.74,5 ; 66.21,42.91 JP8.3 ; JP8.3 68.15,44.85 ; JP8.3 66.21,44.85 ; JP8.3 68.15,42.91 ; 64.85,5.38 JP2.3 64.85,7.32 ; 71.98,35.03 J7.3 ; J7.3 71.98,32.69 ; J7.3 74.32,35.03 ; J7.3 74.32,32.69 ; U8.4 43.36,30.36 ; U8.4 41.27,31.54 ; U8.4 41.27,29.17 ; U8.4 39.19,30.36 ; 46.43,52.78 J6.2 46.43,50.34 ; 67.9,5.38 JP3.3 67.9,7.32 ; R31.1 39.73,24.98 ; R31.1 38.74,23.62 ; R31.1 40.71,23.62 ; R31.1 39.73,22.26 ; 58.96,51.92 K1.16 56.87,51.92 ; 57.15,5.29 R11.2 ; R11.2 58.51,6.25 ; R11.2 57.15,7.21 ; 48.01,46.36 R29.1 ; R29.1 48.01,48.33 ; R29.1 46.64,47.35 ; C10.1 15.41,42.29 ; C10.1 14.64,40.7 ; C10.1 14.64,43.89 ; 30.55,33.1 C19.2 ; C19.2 32.26,34.71 ; C19.2 33.97,33.1 ; C19.2 32.26,31.49 ; 49.84,26.63 C11.2 ; C11.2 51.44,25.87 ; C11.2 53.03,26.63 ; U13.1 58.27,48.39 ; U13.1 56.81,49.15 ; U13.1 55.35,48.39 ; 19.13,53.16 J4.2 19.13,50.72 ; 48.86,32 C22.2 49.62,33.6 ; 60.45,50.04 J5.2 ; J5.2 61.89,48.6 ; J5.2 61.89,51.48 ; R20.2 59.36,37.59 ; R20.2 58.4,38.95 ; R20.2 57.44,37.59 ; J1.13 67.92,26.6 ; J1.13 67.92,24.51 ; J1.13 65.83,26.6 ; 42.19,3.81 C3.2 41.16,2.62 ; 52.49,21.69 R7.2 ; 44.51,3.97 C12.2 ; 18.46,7.53 J2.3
  vias: v1(1.65,32.77) v1(1.65,31.5) v1(1.65,30.23) v1(1.65,28.96) v1(1.78,39.12) v1(10.83,14.06) v1(10.83,1.05) v1(11.18,34.04) v1(11.3,31.5) v1(11.3,30.23) v1(11.3,28.96) v1(11.65,15.84) v1(11.78,21.31) v1(15.49,40.39) v1(19.18,37.47) v1(20.57,46.1) v1(22.86,37.08) v1(22.86,36.2) v1(23.37,35.18) v1(23.88,37.08) v1(23.88,36.2) v1(24.89,17.14) v1(24.98,23.84) v1(26.67,15.24) v1(30.86,36.07) v1(30.86,35.18) v1(31.75,36.07) v1(31.75,35.18) v1(31.75,5.33) v1(32.64,36.07) v1(32.64,35.18) v1(33.53,36.07) v1(33.53,35.18) v1(34.29,21.34) v1(35.18,6.35) v1(41.16,2.17) v1(41.53,23.62) v1(41.91,14.48) v1(44.32,3.94) v1(44.45,6.73) v1(44.58,14.48) v1(44.58,13.21) v1(44.7,28.45) v1(44.7,27.18) v1(44.7,25.91) v1(44.7,24.77) v1(48.01,9.27) v1(48.64,20.83) v1(49.15,27.05) v1(49.66,15.75) v1(49.78,21.97) v1(49.91,19.05) v1(52.7,12.32) v1(52.83,10.79) v1(59.18,5.97) v1(59.31,8.38) v1(59.56,20.95) v1(59.69,38.48) v1(62.1,39.24) v1(70.36,28.57) v1(70.61,23.37) v1(73.66,18.03)
BATT: length 57.4
  TOP w0.178: U9.5 62.04,44.28 v1(61.49,44.83)
  TOP w0.508: U11.7 v1(28.45,38.35)
  BOTTOM w0.178: v1(61.49,44.83) R18.2
  BOTTOM w0.508: v1(28.45,38.35) 28.57,38.23 R22.1 ; 59.31,45.85 U13.3
  BOTTOM w0.762: R18.2 60.07,46.61 59.31,45.85 59.31,44.2 K1.12 57.91,40.78 56.78,39.65 R30.2 54.12,39.65 53.95,39.47 R19.1 36.32,39.47 ; v1(28.45,38.35) 29.39,39.29 C19.1 32.71,39.29 32.89,39.47 36.32,39.47 ; 36.32,39.47 C15.1 38.57,35.16 38.97,35.56 U8.1
BATT_CURR: length 56.6
  TOP w0.178: v1(40.77,27.18) 44.58,30.99 49.91,30.99 51.94,33.02 59.94,33.02 62.99,36.07 U9.2 ; U2.23 v1(30.29,11.11)
  BOTTOM w0.178: v1(30.29,11.11) 30.29,11.87 32.24,13.82 32.24,18.01 32.89,18.67 32.89,24.13 35.43,26.67 40.26,26.67 v1(40.77,27.18)
BATT_VOLT: length 45.6
  TOP w0.178: U2.24 31.09,9.63 31.62,10.16 v1(31.62,11.18)
  BOTTOM w0.178: v1(31.62,11.18) 31.62,12.19 32.59,13.16 32.59,17.86 33.53,18.8 33.53,24 35.69,26.16 40.77,26.16 44.58,29.97 53.72,29.97 54.42,30.67 U10.4 54.42,32.89 54.16,33.15 52.7,33.15 52.52,33.33 U10.1
CAM_ON_OFF: length 56.3
  TOP w0.178: v1(44.2,42.93) 44.96,43.69 U12.2 ; v1(30.61,13.97) 30.61,13.21 29.84,12.45 U2.19
  BOTTOM w0.178: 45.85,44.35 R24.2 45.09,43.81 v1(44.2,42.93) 28.7,42.93 26.92,41.15 26.92,33.02 32.38,27.56 32.38,18.92 31.88,18.41 31.88,15.24 v1(30.61,13.97)
LED_CNTL: length 41.9
  TOP w0.178: v1(58.93,47.12) 53.98,42.16 53.98,41.15 46.61,33.78 44.96,33.78 36.69,25.51 v1(36.69,21.45) U2.3
  BOTTOM w0.178: v1(58.93,47.12) U13.2 ; R31.2 36.73,22.5 36.69,22.47 v1(36.69,21.45)
LED_STATE: length 33.5
  TOP w0.178: K1.5 50.29,38.48 46.48,34.67 44.83,34.67 35.89,25.73 U2.4
  BOTTOM w0.381: K1.5 48.51,42.8 48.01,43.31 R29.2
LED_TRIG: length 50.6
  TOP w0.178: J7.1 71.37,38.86 69.72,37.21 65.28,37.21 60.58,32.51 52.7,32.51 50.55,30.35 44.83,30.35 42.8,28.32 42.8,22.73 41.53,21.46 37.97,21.46 37.49,20.98 U2.2
  BOTTOM w0.178: R28.2 71.93,38.88 71.96,38.86 J7.1
N14907254: length 28.5
  TOP w0.178: 19.68,12.04 25.38,12.04 26.58,13.25 U2.18 ; 19.68,12.04 J2.1 ; 19.68,12.04 SW1.1 SW1.3
  BOTTOM w0.178: J2.1 19.68,10.84 19.2,11.33 R4.1
N14907334: length 23.2
  TOP w0.178: U2.25 v1(31.89,6.62) ; U1.1 v1(48.9,2.67)
  BOTTOM w0.178: v1(48.9,2.67) 48.9,3.68 47.75,4.83 44.58,4.83 44.3,5.11 33.4,5.11 v1(31.89,6.62)
N14907346: length 20.9
  TOP w0.178: v1(41.91,15.88) 43.56,17.53 43.56,19.43 44.96,20.83 U3.2 ; U2.26 v1(32.69,10.21)
  BOTTOM w0.178: v1(41.91,15.88) 36.25,10.21 v1(32.69,10.21)
N14907358: length 20.2
  TOP w0.178: U1.3 v1(48.9,5.21) ; U2.27 v1(33.49,6.1)
  BOTTOM w0.178: v1(48.9,5.21) 44.7,5.21 44.45,5.46 34.12,5.46 v1(33.49,6.1)
N14907370: length 12.7
  TOP w0.178: U2.36 41.31,11.65 44.58,8.38 47.88,8.38 48.51,7.75 U1.5
N14907460: length 6.9
  TOP w0.178: Q1.1 58.41,11.24 58.22,11.05 v1(57.15,11.05)
  BOTTOM w0.178: v1(57.15,11.05) R11.1 R10.2
N14907464: length 17.8
  TOP w0.178: U2.38 v1(41.69,13.25)
  BOTTOM w0.178: v1(41.69,13.25) 48.69,6.25 R10.1 54.86,6.25
N14907857: length 2.9
  TOP w0.178: J1.2 63.32,10.31 63.3,10.29 Q1.3
N14907883: length 27
  TOP w0.178: 51.09,3.94 56.01,3.94 57.13,5.05 59.66,5.05 62.99,8.38 67.57,8.38 68.58,9.39 68.58,11.15 J1.3
  BOTTOM w0.178: J1.3 67.89,12.85 68.27,13.23 R1.1
N14907926: length 24.1
  TOP w0.178: U3.3 v1(48.39,19.56)
  BOTTOM w0.178: J1.5 65.63,16.64 60.07,16.64 59.05,17.65 55.88,17.65 55.37,18.16 55.37,19.81 54.74,20.45 49.8,20.45 48.91,19.56 v1(48.39,19.56)
N14907967: length 23.6
  TOP w0.178: J1.6 63.32,15.39 63.3,15.37 62.36,15.37 59.05,12.06 55.88,12.06 53.59,9.78 53.59,7.62 52.45,6.48 U1.4
  BOTTOM w0.178: R2.1 61.09,14.35 62.13,15.39 J1.6
N14907987: length 22.5
  TOP w0.178: U1.6 52.32,9.02 55.73,12.42 58.14,12.42 62.36,16.64 65.58,16.64 J1.7
  BOTTOM w0.178: J1.7 67.89,17.93 67.9,17.93 R3.1
N14908751: length 2.6
  TOP w0.305: JP2.1 62.96,2.35 62.9,2.29 R9.2
N14908758: length 2.6
  TOP w0.305: R12.2 68.77,2.29 68.71,2.35 JP3.1
N14908817: length 7.1
  BOTTOM w0.178: J1.1 65.53,8.97 65.53,5.74 JP3.2
N14908823: length 10.6
  BOTTOM w0.178: JP2.2 62.84,4.35 62.36,4.83 62.36,8.13 62.74,8.51 62.74,11.25 J1.4
N14908912: length 10.6
  TOP w0.178: JP4.2 58.04,27.14 58.04,25.65 57.4,25.02 54.86,25.02 54.48,24.64 U7.5
N14908949: length 11.8
  TOP w0.178: U7.6 50.04,25.91 49.4,25.27 49.4,24 50.16,23.24 53.98,23.24 55.73,21.49 JP5.2
N14908956: length 24.6
  TOP w0.178: U2.1 v1(39.43,19.75)
  BOTTOM w0.178: JP4.1 59.44,25.53 58.95,25.04 R15.1 46.63,25.04 45.34,23.75 43.43,23.75 v1(39.43,19.75)
N14909000: length 30.4
  TOP w0.178: U2.44 v1(41.52,18.05)
  BOTTOM w0.178: JP5.1 55.12,21.02 55.12,22.99 54.71,23.39 44.35,23.39 41.52,20.56 v1(41.52,18.05) 38.24,18.05 36.93,16.74 R16.1
N14909094: length 13.5
  BOTTOM w0.178: JP4.3 61.15,30.54 61.72,29.97 61.72,24.89 62.36,24.26 65.63,24.26 J1.11
N14909112: length 7.9
  BOTTOM w0.178: J1.12 60.71,23.01 60.23,23.49 JP5.3
N14910852: length 10.4
  TOP w0.178: Y1.2 v1(37.47,3.81) 36.69,4.58 U2.31
  BOTTOM w0.178: C3.1 v1(37.47,3.81)
N14910856: length 10.5
  TOP w0.178: U2.30 35.89,4.87 35.56,4.54 v1(35.56,3.81) Y1.1
  BOTTOM w0.178: C2.1 v1(35.56,3.81)
N14911169: length 5.3
  TOP w0.178: U4.1 v1(16.08,25.1)
  BOTTOM w0.178: C4.1 15.9,24.17 16.08,24.34 v1(16.08,25.1)
N14911173: length 4.6
  TOP w0.178: U4.4 v1(16.13,21.29)
  BOTTOM w0.178: v1(16.13,21.29) 15.4,21.29 15.36,21.24 C5.1
N14911187: length 4.6
  TOP w0.178: U4.3 v1(16.08,22.56)
  BOTTOM w0.178: C4.2 15.81,22.82 v1(16.08,22.56)
N14911204: length 4.6
  TOP w0.178: U4.5 v1(16.13,20.02)
  BOTTOM w0.178: v1(16.13,20.02) 16.02,19.9 C5.2
N14911399: length 3.7
  TOP w0.178: U4.6 11.33,18.75 11.03,18.45 C7.2
N14911406: length 3.6
  TOP w0.178: C8.1 11.61,23.91 11.69,23.83 U4.2
N14911585: length 9.4
  TOP w0.178: U3.5 v1(48.64,17.02)
  BOTTOM w0.178: R7.1 R6.1 52.73,17 52.7,17.02 v1(48.64,17.02)
N14911707: length 16.3
  TOP w0.178: J1.10 63.32,20.47 63.3,20.45 62.48,20.45 58.04,16 JP1.2
  BOTTOM w0.178: R6.2 53.85,14.99 54.86,16 55.73,16 55.73,16 JP1.2 ; J1.9 J1.10
N14911875: length 3
  BOTTOM w0.178: J1.8 63.32,17.93 63.32,17.93 R5.2
N14916159: length 5.8
  TOP w0.178: JP6.2 55.74,27.57 55.74,27.57 55.34,27.18 U7.7
N14918456: length 21.7
  TOP w0.178: U4.14 v1(20.4,22.56)
  BOTTOM w0.178: v1(20.4,22.56) 16.64,18.8 J3.2
N14918460: length 22.2
  TOP w0.178: v1(20.45,20.57) 21.16,21.29 U4.13
  BOTTOM w0.178: 2.92,16.26 5.71,16.26 6.73,17.27 17.14,17.27 v1(20.45,20.57)
N14934806: length 7.5
  TOP w0.178: U2.14 27.62,16.45 26.04,18.03 26.04,18.8 24.82,20.02 U4.12
N14934816: length 6.8
  TOP w0.178: U4.11 24.52,18.75 27.62,15.65 U2.15
N14937836: length 22.2
  TOP w0.381: U5.16 10.54,35.31 9.65,36.2 9.65,46.74 12.06,49.15 12.57,49.15 J4.1
N14938943: length 2.6
  TOP w0.178: D1.A 75.26,22.05 75.16,21.95 R8.2
N14940001: length 4.1
  TOP w0.178: U2.7 33.49,21.25 33.35,21.39 C9.1
N14968686: length 2.6
  TOP w0.178: R13.2 75.16,16.61 75.26,16.71 D2.A
N14976351: length 45.9
  TOP w0.178: 10.79,40.39 10.79,38.48 11.43,37.85 U5.18 v1(15.62,37.85) ; 10.79,40.39 10.79,43.94 11.68,44.83 13.8,44.83 ; 10.79,40.39 U5.20 ; v1(15.62,27.3) 24.5,27.3 31.09,20.72 U2.10
  BOTTOM w0.178: v1(15.62,27.3) v1(15.62,37.85)
N14991516: length 30.5
  TOP w0.178: 45.07,36.85 45.07,35.8 39.6,30.33 37.82,30.33 TP4.1
  TOP w0.381: D4.C 41.66,38.73 43.54,36.85 R21.1 47.65,36.85 48.51,37.72 48.51,44.45 48.01,44.96 U12.3
N14991548: length 9.9
  TOP w0.381: J6.1 42.67,49.66 43.18,49.15 43.18,46.23 ; U12.5 43.18,46.23 ; 43.18,46.23 43.18,45.43 42.71,44.96 U12.6
N14991564: length 12.9
  TOP w0.381: U12.7 43.31,43.69 ; 43.31,43.69 43.31,42.42 ; 43.31,43.69 43.31,44.58 44.96,46.23 U12.4 ; 43.31,42.42 45.09,40.64 R21.2 ; 43.31,42.42 U12.8
N14993015: length 2.6
  TOP w0.178: D3.A 75.01,27.18 75.03,27.16 R17.2
N14993095: length 11.4
  TOP w0.178: v1(64.52,44.83) 63.94,44.26 U9.4
  BOTTOM w0.178: R18.1 64.52,46.59 v1(64.52,44.83)
  BOTTOM w0.762: TP2.1 66.47,50.93 65.59,50.04 J5.1 64.39,47.86 64.49,47.75 R18.1
N14993373: length 5.9
  BOTTOM w0.178: R20.1 55.39,36.22 55.05,35.87 54.42,35.87 ; 54.42,35.87 U10.3 ; 54.42,35.87 53.82,36.47 R19.2
N14997505: length 14.4
  BOTTOM w0.381: U13.5 50.04,44.58 49.91,44.7 49.91,45.85 ; K1.1 50.29,51.94 49.91,51.56 49.91,50.8 ; 49.91,50.8 49.91,45.85 ; 49.91,50.8 D7.C ; U13.6 49.91,45.85
N14997509: length 12.2
  BOTTOM w0.381: U13.4 55.37,44.58 ; 55.37,44.58 R30.1 55.37,42.52 ; 55.37,44.58 54.23,45.72 54.23,47.12 ; 54.23,47.12 54.23,48.01 53.85,48.39 U13.8 ; 54.23,47.12 U13.7
N14997545: length 17.6
  BOTTOM w0.381: 61.47,35.18 K1.9 ; 61.47,35.18 62.87,35.18 64.05,36.36 J7.2 ; 61.47,35.18 TP5.1
N14997611: length 2.9
  BOTTOM w0.178: JP8.2 68.1,41.88 68.11,41.89 R28.1
N14997833: length 1.5
  BOTTOM w0.381: D7.A D6.A
N15001299: length 14.5
  TOP w0.178: J2.5 19.68,4.11 19.86,3.94 23.95,3.94 24.13,4.11 24.13,6.86 27.32,10.05 U2.22
N15001311: length 8.3
  TOP w0.178: U2.21 27.1,10.85 23.78,7.53 J2.4
N15003009: length 10.5
  TOP w0.178: U3.4 45.09,18.29 43.56,16.76 43.56,13.46 42.55,12.45 U2.37
N15003605: length 41.6
  TOP w0.178: U5.1 5.21,40.39 7.24,38.35 7.24,28.83 9.54,26.53 15.94,26.53 16.34,26.92 24.08,26.92 30.29,20.72 U2.11
N15003639: length 45.1
  TOP w0.178: U2.9 31.89,20.72 24.67,27.94 16.51,27.94 15.24,29.21 15.24,35.69 14.35,36.58 U5.17 11.05,36.58 10.29,37.34 10.29,45.34 11.05,46.1 U6.5
N15003651: length 40.1
  TOP w0.178: U6.2 17.27,43.56 16.38,42.67 16.38,39.12 ; U2.8 32.69,20.78 24.7,28.77 17.21,28.77 16.38,29.59 16.38,37.51 16.4,37.52 16.4,38.17 16.38,38.18 16.38,39.12 ; 16.38,39.12 U5.19
N15003663: length 36.2
  TOP w0.178: U5.6 5.21,34.04 6.22,33.02 6.22,28.57 8.76,26.04 24.26,26.04 28.59,21.7 U2.12
N15007328: length 11.7
  TOP w0.178: R17.1 69.6,26.04 68.96,26.67 68.96,33.02 68.58,33.4 JP7.2
N15010506: length 24
  TOP w0.305: 24.36,39.62 U11.8 ; U11.8 27.28,39.62 ; U11.8 25.82,40.38 ; 26.78,45.12 L1.1 ; L1.1 28.76,48.13 ; L1.1 24.79,48.13 ; L1.1 26.78,51.14 ; 29.23,39.7 D5.C ; D5.C 31.24,41.25 ; D5.C 33.25,39.7 ; 24.11,40.55 C18.2 ; C18.2 25.14,41.91 ; C18.2 23.07,41.91 ; C18.2 24.11,43.27
N15010522: length 35.1
  TOP w0.178: R23.1 27.69,30.99 28.83,29.84 34.04,29.84 35.18,30.99 39.24,30.99 41.66,33.4 D4.A
  TOP w0.381: D4.A 39.65,35.76 37.34,38.08 C20.1 37.34,44.62 36.98,44.98 L1.2
N15010535: length 6.5
  TOP w0.178: U11.4 19.68,35.81 18.69,34.82 R27.1 R26.2
N15010979: length 3.5
  TOP w0.178: U11.2 18.97,38.35 18.11,39.22 C21.1
N15011317: length 2.4
  TOP w0.178: U11.1 20.92,40.6 21.1,40.79 C18.1
N15011830: length 6.9
  TOP w0.178: R25.1 26.39,34.72 25.82,35.3 U11.5 28.07,35.81 v1(28.45,35.43)
  BOTTOM w0.178: R22.2 28.57,34.78 28.45,34.91 v1(28.45,35.43)
N15012683: length 43.2
  TOP w0.178: R13.1 71.41,15.49 69.22,13.29 69.22,9.53 67.69,8 63.11,8 59.81,4.7 57.28,4.7 55.88,3.3 49.36,3.3 48.09,4.57 45.09,4.57 41.31,8.35 U2.33
N15013353: length 18.3
  TOP w0.178: JP1.1 57.56,14 62.74,19.18 68.45,19.18 70.1,20.83 R8.1
N15018313: length 36.7
  TOP w0.178: U2.5 35.09,20.74 35.31,20.95 35.31,26.04 34.29,27.05 v1(31.24,27.05) ; U6.1 18.71,41.77 18.67,41.73 v1(18.67,40.77)
  BOTTOM w0.178: v1(18.67,40.77) 17.91,40.01 17.91,32.26 20.57,29.59 28.7,29.59 v1(31.24,27.05)
N15018357: length 50
  TOP w0.178: v1(15.88,43.56) U6.7 ; U2.35 38.18,10.85 v1(30.61,18.41)
  BOTTOM w0.178: v1(15.88,43.56) 16.89,42.55 16.89,30.86 19.81,27.94 26.92,27.94 30.61,24.26 v1(30.61,18.41)
N15018369: length 52.4
  TOP w0.178: v1(30.61,15.62) 36.2,10.03 36.77,10.03 37.49,9.32 U2.32 ; v1(16.64,44.83) 18.71,44.83
  BOTTOM w0.178: v1(16.64,44.83) 17.4,44.07 17.4,31.62 20.19,28.83 27.18,28.83 31.5,24.51 31.5,16.51 v1(30.61,15.62)
N15023556: length 53.4
  TOP w0.178: U2.34 37.58,10.05 v1(30.61,17.02) ; U5.5 v1(5.84,35.31)
  BOTTOM w0.178: v1(30.61,17.02) 29.46,18.16 29.46,22.61 25.02,27.05 18.16,27.05 17.53,26.42 10.92,26.42 8,29.34 R14.1 6.59,35.33 6.57,35.31 v1(5.84,35.31)
N15039082: length 1.7
  TOP w0.178: R26.1 R23.2

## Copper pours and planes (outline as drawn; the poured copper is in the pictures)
GND_SIGNAL on TOP: 0.64,53.98 0.64,0.64 77.47,0.64 77.47,53.98 ; 33 cut-outs
GND_SIGNAL on BOTTOM: 0.64,0.64 0.64,53.98 77.47,53.98 77.47,0.64 ; 14 cut-outs
GND_SIGNAL on GND1: 0.64,0.64 0.64,53.98 77.47,53.98 77.47,0.64
GND_SIGNAL on GND2: 0.64,53.98 0.64,0.64 77.47,0.64 77.47,53.98
N15010506 on TOP: 22.86,40.64 22.86,51.56 29.59,51.56 29.59,46.48 34.04,42.04 34.04,38.1 28.32,38.1 27.3,39.12 24.38,39.12

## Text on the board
Ref Des/Silkscreen Bottom: MADE IN USA | SCPI CONTROLLER BOARD | 10020902rC | COPYRIGHT MBARI 2012
XSECTION_CHART: PRE-PREG (2X) 2116 (0.0094) | INNER CORE (0.035") | TOP SIG/GND LAYER, 2oz CU (0.0027") | GND1 LAYER, 1oz CU (0.00135") | GND2 LAYER, 1oz CU (0.00135") | BOTTOM SIG/PWR LAYER, 2oz CU (0.0027") | PREFERRED STACKUP | FIGURE | SIZE | 10.0 | 32.0 | 34.0 | 39.0 | 42.0 | 43.0 | 47.0 | 63.0 | 126.0 | DRILL CHART: TOP to BOTTOM | ALL UNITS ARE IN MILS | PLATED | QTY | 121 | 4 | 18 | 6 | 22 | 8 | 5
